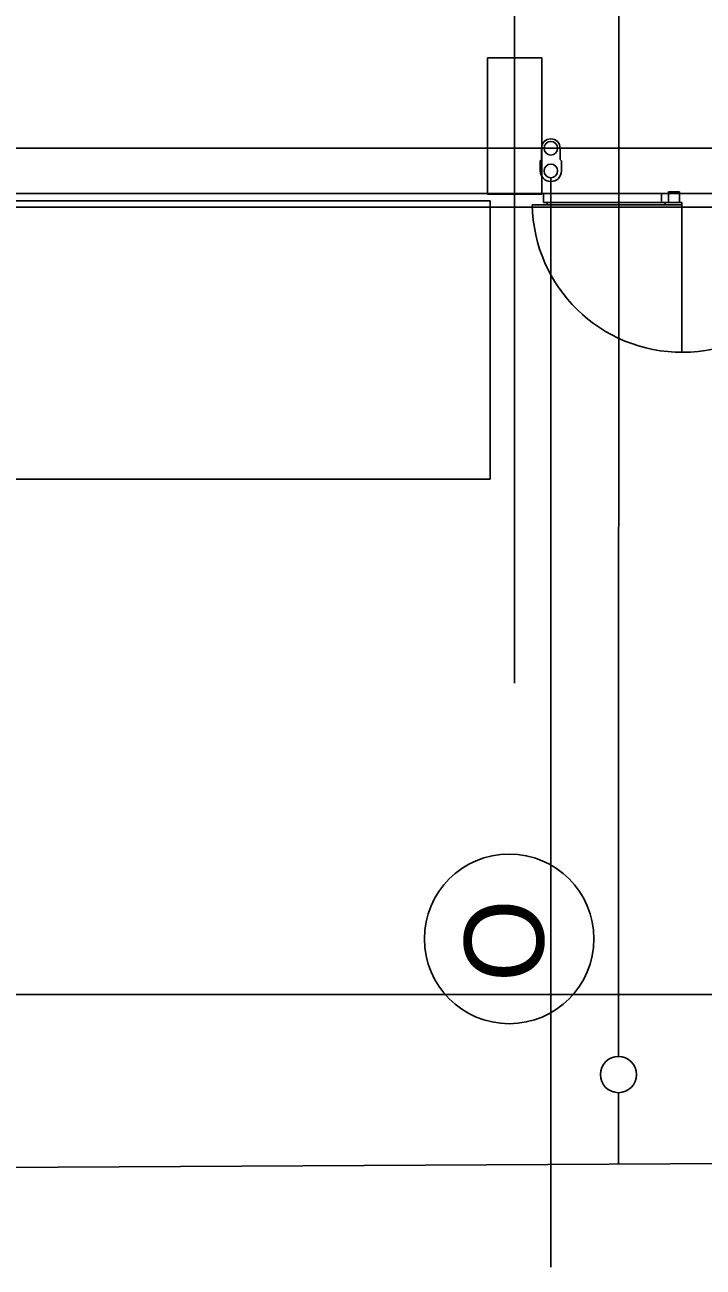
# Model space of a CAD drawing. Extents: x -264031 to -263588, y -1242281 to -1242059.
# Drawn here: x -263824.87 to -263817.39, y -1242253.15 to -1242239.45 of the extents above; entities that cross this region are included whole.
import ezdxf

# ---------------------------------------------------------------- set-up
doc = ezdxf.new("R2010")
doc.units = 0
for name, color, linetype in [('HESCON_OSI_STAVBY_KFA', 7, 'Continuous'), ('KFA_2D_SITUACIA_DSP', 7, 'Continuous'), ('KFA_JESTV_IS_DSP_-_KANAL_SPLASK', 7, 'Continuous')]:
    doc.layers.add(name, color=color, linetype=linetype)

msp = doc.modelspace()

# ---------------------------------------------------------------- linework, layer by layer
at = {"layer": 'HESCON_OSI_STAVBY_KFA'}
for p, q in [((-263819.468, -1242083.237), (-263819.468, -1242246.707)), ((-263792.653, -1242240.807), (-263911.523, -1242240.807))]:
    msp.add_line(p, q, dxfattribs=at)
msp.add_circle((-263819.528, -1242249.526), 0.935, dxfattribs=at)
at = {"layer": 'KFA_2D_SITUACIA_DSP'}
for p, q in [((-263818.318, -1242235.757), (-263818.321, -1242250.822)), ((-263819.768, -1242241.312), (-263819.768, -1242239.812)), ((-263819.768, -1242239.812), (-263819.168, -1242239.812)), ((-263819.168, -1242239.812), (-263819.168, -1242241.312)), ((-263819.171, -1242240.807), (-263819.171, -1242240.932)), ((-263818.965, -1242240.807), (-263818.965, -1242240.932)), ((-263819.171, -1242240.932), (-263819.185, -1242240.946)), ((-263819.185, -1242240.946), (-263819.185, -1242241.057)), ((-263818.965, -1242240.932), (-263818.951, -1242240.946)), ((-263818.951, -1242240.946), (-263818.951, -1242241.057)), ((-263818.951, -1242241.057), (-263818.951, -1242240.946)), ((-263819.068, -1242241.132), (-263819.068, -1242253.146)), ((-263894.581, -1242241.307), (-263809.355, -1242241.307)), ((-263819.738, -1242241.388), (-263827.188, -1242241.388)), ((-263819.168, -1242241.312), (-263819.768, -1242241.312)), ((-263819.738, -1242244.458), (-263819.738, -1242241.388)), ((-263819.068, -1242241.307), (-263819.148, -1242241.307)), ((-263819.148, -1242241.307), (-263819.148, -1242241.407)), ((-263819.068, -1242241.407), (-263819.068, -1242241.307)), ((-263817.848, -1242241.407), (-263817.848, -1242241.307)), ((-263817.848, -1242241.307), (-263817.768, -1242241.307)), ((-263817.648, -1242241.287), (-263817.768, -1242241.287)), ((-263817.768, -1242241.287), (-263817.768, -1242241.407)), ((-263817.768, -1242241.307), (-263817.768, -1242241.407)), ((-263817.648, -1242241.407), (-263817.648, -1242241.287)), ((-263819.273, -1242241.432), (-263817.623, -1242241.432)), ((-263819.148, -1242241.407), (-263819.108, -1242241.407)), ((-263819.108, -1242241.432), (-263819.108, -1242241.407)), ((-263819.108, -1242241.407), (-263817.808, -1242241.407)), ((-263819.108, -1242241.407), (-263819.068, -1242241.407)), ((-263817.808, -1242241.432), (-263819.108, -1242241.432)), ((-263817.808, -1242241.407), (-263817.848, -1242241.407)), ((-263817.808, -1242241.407), (-263817.808, -1242241.432)), ((-263817.768, -1242241.407), (-263817.808, -1242241.407)), ((-263817.768, -1242241.407), (-263817.648, -1242241.407)), ((-263817.648, -1242241.407), (-263817.623, -1242241.407)), ((-263817.623, -1242241.407), (-263817.623, -1242243.057)), ((-263827.188, -1242244.458), (-263819.738, -1242244.458)), ((-263924.143, -1242250.14), (-263788.143, -1242250.14)), ((-263818.322, -1242251.222), (-263818.322, -1242252.009))]:
    msp.add_line(p, q, dxfattribs=at)
msp.add_lwpolyline([(-263794.893, -1242227.382), (-263808.968, -1242241.457), (-263894.968, -1242241.457), (-263909.043, -1242227.382), (-263909.043, -1242196.333), (-263914.143, -1242196.333), (-263914.143, -1242132.433), (-263909.043, -1242132.433), (-263909.043, -1242101.382), (-263894.968, -1242087.307), (-263808.968, -1242087.307), (-263794.893, -1242101.382), (-263794.893, -1242227.382)], dxfattribs=at)
for centre, radius in [((-263819.068, -1242240.807), 0.075), ((-263819.068, -1242241.057), 0.075), ((-263818.322, -1242251.022), 0.2)]:
    msp.add_circle(centre, radius, dxfattribs=at)
for centre, radius, start, end in [((-263819.068, -1242240.807), 0.103, 360, 180), ((-263819.068, -1242241.057), 0.117, 180, 360), ((-263817.623, -1242241.407), 1.65, 180.8682, 0)]:
    msp.add_arc(centre, radius, start, end, dxfattribs=at)
at = {"layer": 'KFA_JESTV_IS_DSP_-_KANAL_SPLASK'}
msp.add_line((-263792.798, -1242251.862), (-263831.703, -1242252.086), dxfattribs=at)

# ---------------------------------------------------------------- texts
at = {"layer": 'HESCON_OSI_STAVBY_KFA'}
msp.add_text('O', height=0.875, rotation=90, dxfattribs=at).set_placement((-263819.147, -1242250.001))

doc.saveas('drawing.dxf')
